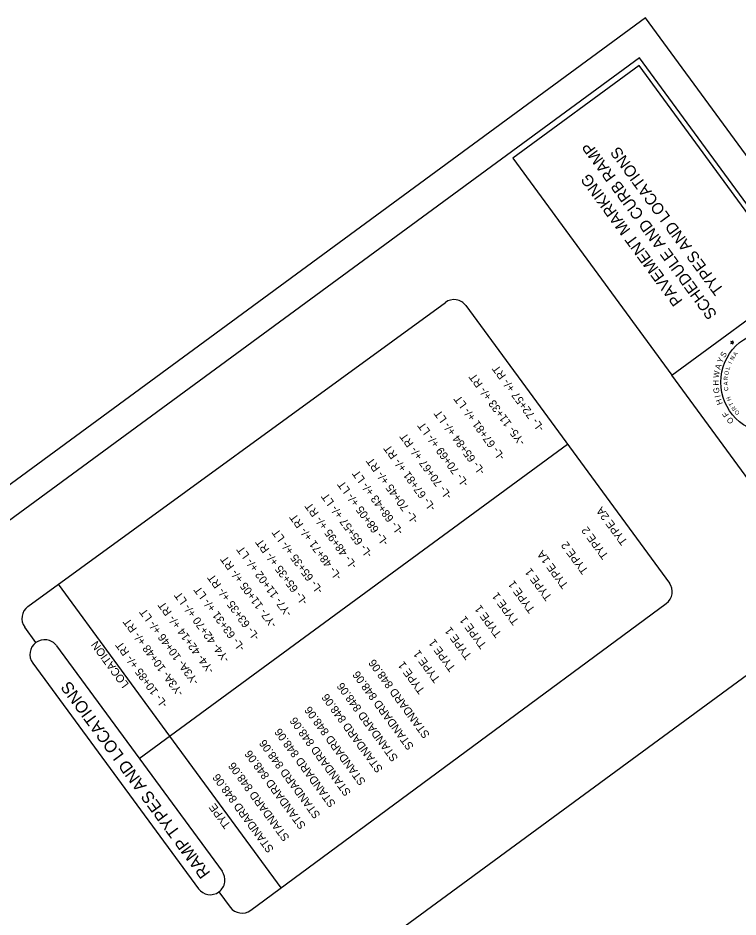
# Model space of a CAD drawing. Extents: x 719153 to 721402, y 581205 to 583188.
# Drawn here: x 720079.9 to 720458.9, y 582492.9 to 582965.9 of the extents above; entities that cross this region are included whole.
import ezdxf

# ---------------------------------------------------------------- set-up
doc = ezdxf.new("R2010")
doc.units = 0
for name, color, linetype in [('Default', 7, 'Continuous'), ('Old_Level_1', 7, 'Continuous'), ('Old_Level_50', 7, 'Continuous'), ('Old_Level_52', 7, 'Continuous'), ('Scratch_Level_9', 7, 'Continuous'), ('Sheet Plot Border Inside CELL', 7, 'Continuous'), ('Sheet Plot Border Outside CELL', 7, 'Continuous'), ('Sheet Sticker Incomplete CELL', 7, 'Continuous')]:
    doc.layers.add(name, color=color, linetype=linetype)

msp = doc.modelspace()

# ---------------------------------------------------------------- linework, layer by layer
at = {"layer": 'Default'}
for p, q in [((720085.13, 582656.15), (720304.87, 582816.21)), ((720315.65, 582814.51), (720422.77, 582668.59)), ((720143.74, 582576.27), (720369.14, 582741.64)), ((720159.86, 582588.09), (720101.29, 582667.92)), ((720202.38, 582496.41), (720421.13, 582657.78)), ((720089.36, 582637.28), (720083.45, 582645.35)), ((720100.17, 582635.62), (720187.31, 582516.92)), ((720087.67, 582626.45), (720174.85, 582507.77)), ((720218.42, 582508.26), (720159.86, 582588.09)), ((720185.65, 582506.11), (720191.57, 582498.05))]:
    msp.add_line(p, q, dxfattribs=at)
for centre, start, end in [((720309.41, 582809.95), 36.1667, 126.1667), ((720416.54, 582664), 306.3666, 36.3666), ((720089.69, 582649.91), 126.1667, 216.1667), ((720093.93, 582631.05), 126.2667, 216.2667), ((720093.93, 582631.05), 36.2667, 126.2667), ((720181.08, 582512.34), 306.2666, 36.2666), ((720181.08, 582512.34), 216.2666, 306.2666), ((720197.8, 582502.63), 216.3666, 306.3666)]:
    msp.add_arc(centre, 7.73, start, end, dxfattribs=at)
at = {"layer": 'Old_Level_50'}
msp.add_lwpolyline([(721009.35, 582149.27), (720410.24, 582965.86), (719878.1, 582575.44), (720477.21, 581758.85)], close=True, dxfattribs=at)
at = {"layer": 'Old_Level_52'}
msp.add_circle((720476.81, 582774.23), 26.98, dxfattribs=at)
at = {"layer": 'Scratch_Level_9'}
for p, q in [((720455.04, 582795.69), (720455.42, 582795.16)), ((720455.66, 582795.49), (720455.04, 582795.69)), ((720455.42, 582795.16), (720455.07, 582794.63)), ((720455.07, 582794.63), (720455.67, 582794.83)), ((720456.05, 582796.01), (720455.66, 582795.49)), ((720455.67, 582794.83), (720456.05, 582794.31)), ((720456.06, 582795.36), (720456.05, 582796.01)), ((720456.05, 582794.96), (720456.67, 582795.18)), ((720456.05, 582794.31), (720456.05, 582794.96)), ((720456.67, 582795.18), (720456.06, 582795.36))]:
    msp.add_line(p, q, dxfattribs=at)
at = {"layer": 'Sheet Plot Border Inside CELL'}
msp.add_lwpolyline([(719899.07, 582572.22), (720431.46, 581846.57), (720939.41, 582219.25), (720407.02, 582944.89)], close=True, dxfattribs=at)
at = {"layer": 'Sheet Plot Border Outside CELL'}
for points in [[(720340.26, 582892.08), (720424.03, 582777.92), (720490.54, 582826.72), (720406.78, 582940.89)], [(720464.49, 582722.76), (720424.03, 582777.92), (720490.54, 582826.72), (720531.01, 582771.57)]]:
    msp.add_lwpolyline(points, close=True, dxfattribs=at)
at = {"layer": 'Sheet Sticker Incomplete CELL'}
msp.add_line((720116.85, 582365.91), (720504.77, 582650.51), dxfattribs=at)

# ---------------------------------------------------------------- texts
at = {"layer": 'Default'}
for s, height, p in [('LOCATION', 4.21, (720138.48, 582615.3)), ('RAMP TYPES AND LOCATIONS', 6.315, (720181.4, 582516.01)), ('TYPE', 4.21, (720192.13, 582541.25))]:
    msp.add_text(s, height=height, rotation=126.2265, dxfattribs=at).set_placement(p)
at = {"layer": 'Old_Level_1'}
for s, p in [('-L- 72+57 +/- RT', (720357.12, 582750.14)), ('-Y5- 11+33 +/- RT', (720347.12, 582742.8)), ('-L- 67+81 +/- LT', (720336.44, 582734.96)), ('-L- 65+84 +/- LT', (720325.99, 582727.3)), ('-L- 70+69 +/- LT', (720317.34, 582720.95)), ('-L- 70+67 +/- RT', (720308.48, 582714.45)), ('-L- 67+81 +/- RT', (720300, 582708.23)), ('-L- 70+45 +/- RT', (720290.88, 582701.54)), ('-L- 68+43 +/- LT', (720282.94, 582695.71)), ('-L- 68+05 +/- LT', (720275.16, 582690)), ('-L- 65+57 +/- LT', (720266.66, 582683.64)), ('-L- 48+95 +/- RT', (720258.57, 582677.83)), ('TYPE 2A', (720400.96, 582690.38)), ('-L- 48+71 +/- RT', (720250.51, 582671.92)), ('TYPE 2', (720390.97, 582683.04)), ('-L- 65+35 +/- LT', (720240.68, 582664.71)), ('-Y7- 11+02 +/- LT', (720224.33, 582652.71)), ('-L- 65+35 +/- RT', (720232.61, 582658.79)), ('TYPE 2', (720380.28, 582675.2)), ('TYPE 1A', (720369.84, 582667.54)), ('-Y7- 11+05 +/- RT', (720216.35, 582646.86)), ('TYPE 1', (720361.18, 582661.19)), ('-L- 63+35 +/- RT', (720207.29, 582640.21)), ('TYPE 1', (720352.32, 582654.69)), ('-L- 63+31 +/- LT', (720199.57, 582634.55)), ('TYPE 1', (720343.84, 582648.47)), ('-Y4- 42+70 +/- LT', (720191.51, 582628.63)), ('-Y3A- 10+46 +/- LT', (720175.38, 582616.8)), ('-Y4- 42+14 +/- RT', (720183.45, 582622.72)), ('TYPE 1', (720334.73, 582641.78)), ('TYPE 1', (720326.78, 582635.95)), ('-Y3A- 10+48 +/- RT', (720167.32, 582610.89)), ('TYPE 1', (720319, 582630.24)), ('-L- 10+85 +/- RT', (720158.92, 582604.73)), ('TYPE 1', (720310.51, 582623.88)), ('TYPE 1', (720302.41, 582618.07)), ('STANDARD 848.06', (720296.86, 582588.78)), ('TYPE 1', (720294.35, 582612.16)), ('STANDARD 848.06', (720288.45, 582582.62)), ('STANDARD 848.06', (720280.17, 582576.54)), ('STANDARD 848.06', (720272.19, 582570.68)), ('STANDARD 848.06', (720263.13, 582564.03)), ('STANDARD 848.06', (720255.41, 582558.37)), ('STANDARD 848.06', (720247.35, 582552.46)), ('STANDARD 848.06', (720239.28, 582546.54)), ('STANDARD 848.06', (720231.66, 582540.95)), ('STANDARD 848.06', (720223.04, 582534.62)), ('STANDARD 848.06', (720214.79, 582528.57))]:
    msp.add_text(s, height=4.21, rotation=126.2265, dxfattribs=at).set_placement(p)
at = {"layer": 'Old_Level_52'}
msp.add_text('T', height=2.18, rotation=120.0551, dxfattribs=at).set_placement((720456.65, 582762.43))
at = {"layer": 'Scratch_Level_9'}
for s, height, rotation, p in [('Y', 3.02, 66.015, (720450.51, 582783.96)), ('S', 3.02, 59.4916, (720451.83, 582786.89)), ('N', 2.18, 59.118, (720456.31, 582785.45)), ('A', 2.18, 54.04, (720457.71, 582787.66)), ('A', 3.02, 73.0429, (720449.48, 582780.66)), ('L', 2.18, 74.3523, (720454.35, 582780.61)), ('I', 2.18, 64.1961, (720455.45, 582783.68)), ('W', 3.02, 82.0799, (720448.75, 582776.27)), ('R', 2.18, 84.5085, (720453.44, 582775.16)), ('O', 2.18, 79.4304, (720453.71, 582777.75)), ('H', 3.02, 89.7299, (720448.69, 582772.51)), ('A', 2.18, 89.5866, (720453.45, 582772.57)), ('G', 3.02, 97.7834, (720449.16, 582768.57)), ('C', 2.18, 99.7427, (720453.87, 582769.83)), ('I', 3.02, 102.0707, (720449.63, 582766.52)), ('H', 3.02, 109.7207, (720450.86, 582762.95)), ('H', 2.18, 109.8989, (720455.39, 582764.81)), ('F', 3.02, 123.5242, (720454.22, 582757.06)), ('R', 2.18, 125.1331, (720458.19, 582760.11)), ('O', 2.18, 130.2112, (720459.91, 582758.05)), ('O', 3.02, 132.0316, (720456.95, 582753.89))]:
    msp.add_text(s, height=height, rotation=rotation, dxfattribs=at).set_placement(p)
at = {"layer": 'Sheet Plot Border Inside CELL'}
for s, p in [('SCHEDULE AND CURB RAMP', (720448.1, 582809.97)), ('TYPES AND LOCATIONS', (720451.7, 582822.81)), ('PAVEMENT MARKING ', (720429.94, 582816.97))]:
    msp.add_text(s, height=6, rotation=126.2667, dxfattribs=at).set_placement(p)

doc.saveas('drawing.dxf')
